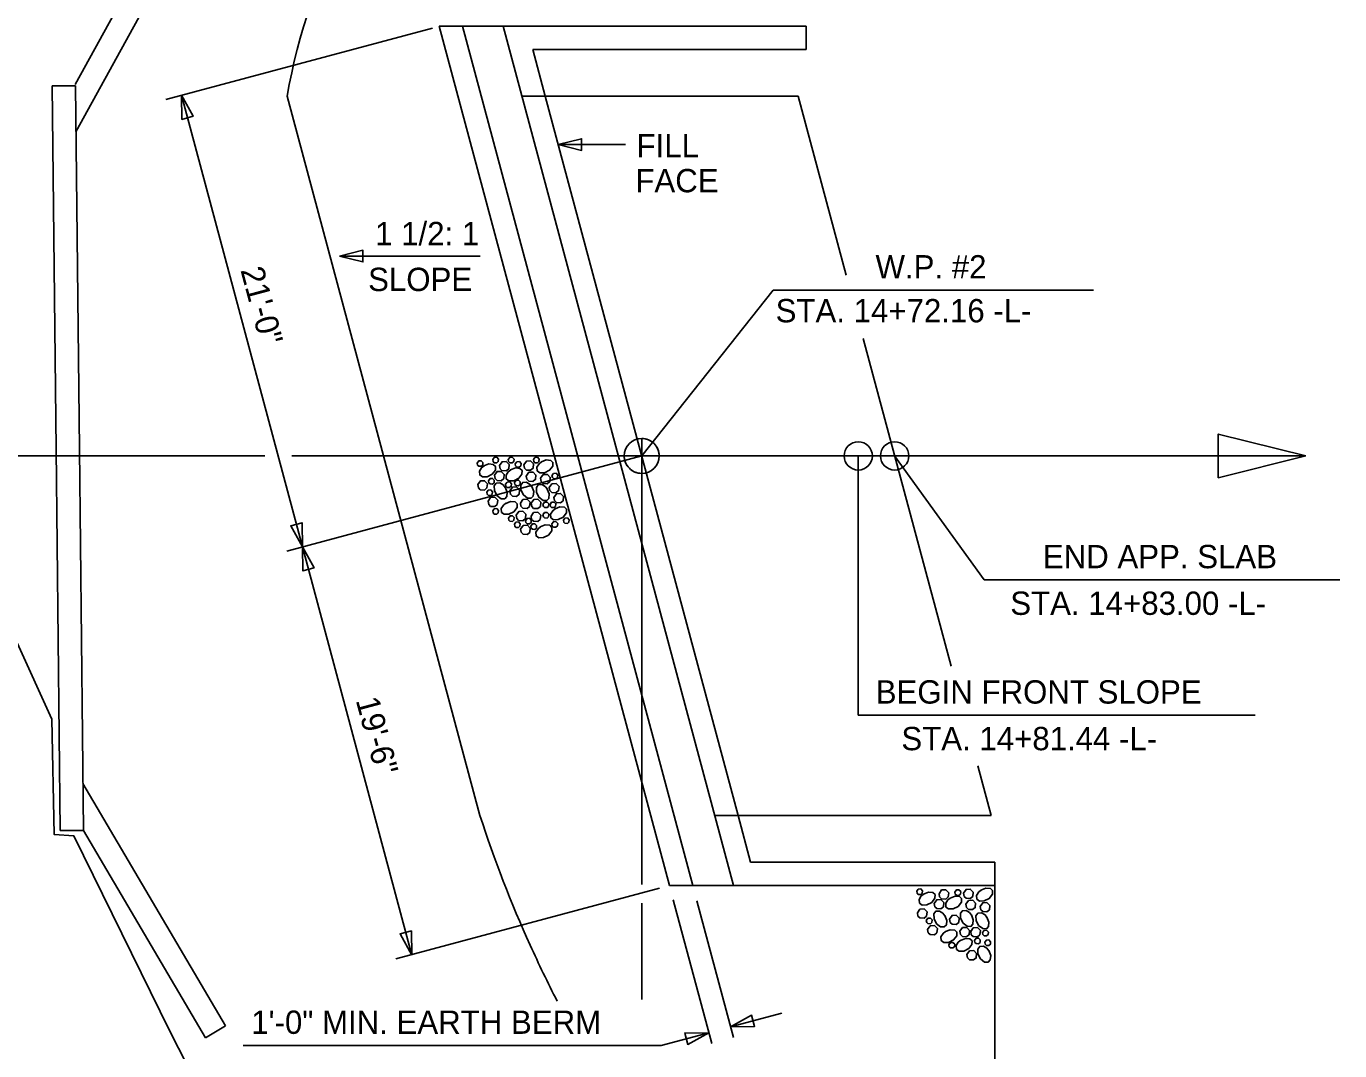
# Model space of a CAD drawing. Extents: x -20 to 509, y -659 to 21.
# Drawn here: x 139.4 to 195.7, y -130 to -86.1 of the extents above; entities that cross this region are included whole.
import ezdxf

# ---------------------------------------------------------------- set-up
doc = ezdxf.new("R2010")
doc.units = 0
for name, color, linetype in [('Arrowhead Terminators CELL', 7, 'Continuous'), ('Auto Dimensioning', 7, 'Continuous'), ('Dimension Lines', 7, 'Continuous'), ('Exist Hydro Stream or Body of Water', 7, 'Continuous'), ('Exist Structure Major Bridge Seam', 7, 'Continuous'), ('Mis Object Lines', 7, 'Continuous'), ('Mis Object Lines Hidden', 7, 'Continuous'), ('Mis Work Point CELL', 7, 'Continuous'), ('Miscellaneous Lines CELL', 7, 'Continuous'), ('Prop Horizontal Alignment', 7, 'Continuous'), ('Sup Concrete Girder Lines', 7, 'Continuous'), ('Text', 7, 'Continuous'), ('User Information Notes', 7, 'Continuous')]:
    doc.layers.add(name, color=color, linetype=linetype)

msp = doc.modelspace()

# ---------------------------------------------------------------- linework, layer by layer
at = {"layer": 'Arrowhead Terminators CELL'}
for points in [[(146.012, -89.031), (146.029, -90.062), (146.512, -89.933)], [(146.012, -89.031), (146.029, -90.062), (146.512, -89.933)], [(162.164, -91.147), (163.164, -91.397), (163.164, -90.897)], [(152.793, -95.923), (153.793, -95.673), (153.793, -96.173)], [(194.198, -104.489), (190.448, -103.552), (190.448, -105.427)], [(151.198, -108.386), (151.18, -107.355), (150.697, -107.484)], [(151.198, -108.386), (151.215, -109.416), (151.698, -109.287)], [(155.886, -125.884), (155.869, -124.853), (155.386, -124.982)], [(169.548, -128.965), (170.578, -128.948), (170.449, -128.465)], [(168.615, -129.215), (167.584, -129.232), (167.713, -129.715)]]:
    msp.add_lwpolyline(points, close=True, dxfattribs=at)
at = {"layer": 'Auto Dimensioning'}
for p, q in [((165.739, -104.989), (165.739, -122.863)), ((165.739, -123.655), (165.739, -127.786))]:
    msp.add_line(p, q, dxfattribs=at)
at = {"layer": 'Dimension Lines'}
for p, q in [((145.337, -89.212), (156.767, -86.149)), ((146.012, -89.031), (151.198, -108.386)), ((162.164, -91.147), (165.043, -91.147)), ((158.815, -95.923), (152.793, -95.923)), ((165.739, -104.489), (171.37, -97.384)), ((171.37, -97.384), (185.103, -97.384)), ((150.523, -108.566), (165.739, -104.489)), ((175.019, -104.489), (175.019, -115.606)), ((176.579, -104.489), (180.423, -109.804)), ((151.198, -108.386), (155.886, -125.884)), ((180.423, -109.804), (195.655, -109.804)), ((175.019, -115.606), (192.032, -115.606)), ((155.207, -126.045), (166.496, -123.02)), ((167.089, -123.522), (168.737, -129.671)), ((168.1, -123.562), (169.67, -129.421)), ((169.548, -128.965), (171.751, -128.375)), ((166.567, -129.764), (168.615, -129.215)), ((148.652, -129.764), (166.567, -129.764))]:
    msp.add_line(p, q, dxfattribs=at)
for centre in [(175.019, -104.489), (176.579, -104.489)]:
    msp.add_circle(centre, 0.606, dxfattribs=at)
at = {"layer": 'Exist Hydro Stream or Body of Water'}
msp.add_lwpolyline([(152.818, -143.472), (145.52, -129.155), (141.407, -120.782), (140.558, -120.72), (140.462, -115.767), (134.29, -102.218)], dxfattribs=at)
at = {"layer": 'Exist Structure Major Bridge Seam'}
for p, q in [((141.463, -88.566), (147.188, -78.13)), ((141.492, -90.593), (148.065, -78.611)), ((140.471, -88.632), (141.471, -88.632)), ((141.791, -118.53), (147.902, -128.926)), ((140.819, -120.55), (141.819, -120.55)), ((141.819, -120.55), (147.04, -129.433)), ((147.04, -129.433), (147.902, -128.926))]:
    msp.add_line(p, q, dxfattribs=at)
for points in [[(140.471, -88.632), (140.641, -104.206), (140.819, -120.55)], [(141.471, -88.632), (141.641, -104.206), (141.819, -120.55)]]:
    msp.add_lwpolyline(points, dxfattribs=at)
at = {"layer": 'Mis Object Lines'}
for p, q in [((157.055, -86.072), (172.789, -86.072)), ((157.055, -86.072), (166.924, -122.906)), ((158.055, -86.072), (167.924, -122.906)), ((159.805, -86.072), (169.674, -122.906)), ((172.789, -87.072), (172.789, -86.072)), ((161.072, -87.072), (161.608, -89.072)), ((161.072, -87.072), (172.789, -87.072)), ((172.448, -89.072), (160.608, -89.072)), ((172.448, -89.072), (174.504, -96.746)), ((175.231, -99.459), (178.995, -113.506)), ((180.14, -117.78), (180.71, -119.906)), ((180.71, -119.906), (168.87, -119.906)), ((169.87, -119.906), (170.406, -121.906)), ((180.87, -121.906), (170.406, -121.906)), ((180.87, -122.906), (180.87, -121.906)), ((166.924, -122.906), (180.87, -122.906))]:
    msp.add_line(p, q, dxfattribs=at)
at = {"layer": 'Mis Object Lines Hidden'}
msp.add_line((161.608, -89.072), (169.87, -119.906), dxfattribs=at)
at = {"layer": 'Mis Work Point CELL'}
for p, q in [((165.739, -103.739), (165.739, -104.489)), ((164.989, -104.489), (165.739, -104.489)), ((165.739, -104.489), (165.739, -105.239)), ((165.739, -104.489), (166.489, -104.489)), ((166.489, -104.489), (166.489, -104.489)), ((165.739, -105.239), (165.739, -105.239))]:
    msp.add_line(p, q, dxfattribs=at)
msp.add_circle((165.739, -104.489), 0.75, dxfattribs=at)
for start, end in [(359.997, 89.9989), (180.0011, 270.003)]:
    msp.add_arc((165.739, -104.489), 0.75, start, end, dxfattribs=at)
at = {"layer": 'Miscellaneous Lines CELL'}
for points in [[(158.686, -104.797), (158.753, -104.701), (158.861, -104.695), (158.935, -104.772), (158.924, -104.881), (158.858, -104.936), (158.752, -104.928), (158.702, -104.88), (158.686, -104.797)], [(159.355, -104.65), (159.422, -104.555), (159.529, -104.548), (159.604, -104.626), (159.593, -104.734), (159.527, -104.789), (159.421, -104.782), (159.371, -104.733), (159.355, -104.65)], [(160.018, -104.65), (160.085, -104.555), (160.192, -104.548), (160.267, -104.626), (160.256, -104.734), (160.19, -104.789), (160.084, -104.782), (160.034, -104.733), (160.018, -104.65)], [(160.687, -104.875), (160.799, -104.715), (160.978, -104.705), (161.103, -104.834), (161.085, -105.015), (160.974, -105.107), (160.797, -105.094), (160.714, -105.013), (160.687, -104.875)], [(161.098, -104.65), (161.165, -104.555), (161.272, -104.548), (161.347, -104.626), (161.336, -104.734), (161.27, -104.789), (161.164, -104.782), (161.114, -104.733), (161.098, -104.65)], [(161.439, -104.747), (161.649, -104.664), (161.841, -104.681), (161.933, -104.768), (161.93, -104.924), (161.791, -105.102), (161.576, -105.209), (161.374, -105.213), (161.26, -105.132), (161.249, -104.971), (161.342, -104.826), (161.448, -104.742)], [(158.976, -104.92), (159.186, -104.836), (159.378, -104.853), (159.47, -104.94), (159.467, -105.096), (159.328, -105.274), (159.114, -105.381), (158.911, -105.385), (158.797, -105.304), (158.787, -105.143), (158.879, -104.999), (158.985, -104.914)], [(159.429, -105.321), (159.541, -105.161), (159.72, -105.151), (159.845, -105.28), (159.827, -105.461), (159.716, -105.553), (159.539, -105.54), (159.456, -105.459), (159.429, -105.321)], [(159.64, -104.899), (159.752, -104.74), (159.931, -104.729), (160.055, -104.858), (160.037, -105.039), (159.927, -105.131), (159.75, -105.118), (159.667, -105.038), (159.64, -104.899)], [(160.115, -105.089), (160.325, -105.006), (160.517, -105.023), (160.609, -105.11), (160.606, -105.266), (160.467, -105.443), (160.252, -105.551), (160.05, -105.554), (159.936, -105.473), (159.925, -105.312), (160.018, -105.168), (160.124, -105.084)], [(160.32, -104.834), (160.387, -104.738), (160.495, -104.732), (160.569, -104.809), (160.558, -104.918), (160.492, -104.973), (160.386, -104.965), (160.336, -104.917), (160.32, -104.834)], [(160.793, -105.352), (160.905, -105.193), (161.084, -105.182), (161.208, -105.311), (161.19, -105.492), (161.079, -105.584), (160.903, -105.571), (160.82, -105.491), (160.793, -105.352)], [(161.893, -105.333), (161.96, -105.237), (162.068, -105.231), (162.142, -105.308), (162.132, -105.417), (162.065, -105.472), (161.959, -105.464), (161.909, -105.416), (161.893, -105.333)], [(158.711, -105.721), (158.823, -105.561), (159.002, -105.551), (159.126, -105.68), (159.108, -105.861), (158.998, -105.953), (158.821, -105.94), (158.738, -105.859), (158.711, -105.721)], [(159.172, -105.556), (159.24, -105.461), (159.347, -105.455), (159.422, -105.532), (159.411, -105.64), (159.344, -105.695), (159.238, -105.688), (159.189, -105.639), (159.172, -105.556)], [(159.887, -105.833), (159.97, -106.043), (159.953, -106.235), (159.866, -106.327), (159.71, -106.324), (159.533, -106.185), (159.425, -105.97), (159.422, -105.768), (159.503, -105.654), (159.664, -105.644), (159.808, -105.736), (159.892, -105.842)], [(159.906, -105.706), (159.973, -105.611), (160.081, -105.605), (160.155, -105.682), (160.144, -105.79), (160.078, -105.846), (159.972, -105.838), (159.922, -105.79), (159.906, -105.706)], [(160.088, -105.992), (160.2, -105.832), (160.379, -105.822), (160.504, -105.951), (160.486, -106.132), (160.375, -106.224), (160.198, -106.211), (160.115, -106.13), (160.088, -105.992)], [(160.285, -105.631), (160.352, -105.535), (160.459, -105.529), (160.534, -105.606), (160.523, -105.715), (160.457, -105.77), (160.351, -105.762), (160.301, -105.714), (160.285, -105.631)], [(161.026, -105.806), (161.109, -106.016), (161.092, -106.208), (161.005, -106.3), (160.849, -106.297), (160.671, -106.158), (160.564, -105.943), (160.561, -105.741), (160.642, -105.627), (160.803, -105.616), (160.947, -105.709), (161.031, -105.815)], [(161.69, -105.908), (161.773, -106.117), (161.757, -106.31), (161.67, -106.401), (161.513, -106.399), (161.336, -106.26), (161.228, -106.045), (161.225, -105.843), (161.306, -105.729), (161.467, -105.718), (161.611, -105.81), (161.695, -105.916)], [(161.405, -105.45), (161.517, -105.29), (161.696, -105.28), (161.821, -105.409), (161.803, -105.59), (161.692, -105.682), (161.515, -105.669), (161.432, -105.588), (161.405, -105.45)], [(161.778, -105.839), (161.891, -105.68), (162.069, -105.669), (162.194, -105.798), (162.176, -105.979), (162.065, -106.071), (161.889, -106.058), (161.806, -105.978), (161.779, -105.839)], [(159.096, -106.047), (159.163, -105.952), (159.27, -105.945), (159.345, -106.023), (159.334, -106.131), (159.268, -106.186), (159.162, -106.179), (159.112, -106.13), (159.096, -106.047)], [(159.153, -106.432), (159.265, -106.273), (159.444, -106.263), (159.568, -106.392), (159.55, -106.572), (159.44, -106.664), (159.263, -106.652), (159.18, -106.571), (159.153, -106.432)], [(160.537, -106.511), (160.649, -106.352), (160.828, -106.342), (160.952, -106.471), (160.934, -106.651), (160.824, -106.743), (160.647, -106.731), (160.564, -106.65), (160.537, -106.511)], [(160.998, -106.518), (161.11, -106.359), (161.289, -106.349), (161.413, -106.478), (161.395, -106.658), (161.284, -106.75), (161.108, -106.737), (161.025, -106.657), (160.998, -106.518)], [(161.974, -106.269), (162.086, -106.109), (162.265, -106.099), (162.39, -106.228), (162.372, -106.409), (162.261, -106.501), (162.084, -106.488), (162.001, -106.407), (161.974, -106.269)], [(159.355, -106.849), (159.422, -106.753), (159.529, -106.747), (159.604, -106.825), (159.593, -106.933), (159.527, -106.988), (159.421, -106.981), (159.371, -106.932), (159.355, -106.849)], [(159.912, -106.526), (160.121, -106.443), (160.314, -106.46), (160.405, -106.547), (160.402, -106.703), (160.264, -106.88), (160.049, -106.988), (159.847, -106.991), (159.733, -106.91), (159.722, -106.749), (159.814, -106.605), (159.92, -106.521)], [(160.355, -107.034), (160.467, -106.875), (160.646, -106.864), (160.77, -106.993), (160.752, -107.174), (160.642, -107.266), (160.465, -107.253), (160.382, -107.172), (160.355, -107.034)], [(160.994, -107.074), (161.106, -106.914), (161.285, -106.904), (161.41, -107.033), (161.392, -107.214), (161.281, -107.306), (161.104, -107.293), (161.021, -107.212), (160.994, -107.074)], [(161.507, -106.567), (161.575, -106.472), (161.682, -106.466), (161.757, -106.543), (161.746, -106.651), (161.68, -106.707), (161.574, -106.699), (161.524, -106.651), (161.508, -106.567)], [(161.507, -107.014), (161.575, -106.918), (161.682, -106.912), (161.757, -106.99), (161.746, -107.098), (161.68, -107.153), (161.574, -107.145), (161.524, -107.097), (161.508, -107.014)], [(161.811, -106.567), (161.878, -106.472), (161.986, -106.466), (162.06, -106.543), (162.049, -106.651), (161.983, -106.707), (161.877, -106.699), (161.827, -106.651), (161.811, -106.567)], [(162.024, -106.759), (162.233, -106.676), (162.426, -106.692), (162.518, -106.779), (162.515, -106.936), (162.376, -107.113), (162.161, -107.22), (161.959, -107.224), (161.845, -107.143), (161.834, -106.982), (161.927, -106.838), (162.032, -106.753)], [(160.027, -107.161), (160.094, -107.065), (160.202, -107.059), (160.276, -107.136), (160.265, -107.245), (160.199, -107.3), (160.093, -107.292), (160.043, -107.244), (160.027, -107.161)], [(160.28, -107.42), (160.347, -107.325), (160.455, -107.319), (160.529, -107.396), (160.518, -107.504), (160.452, -107.559), (160.346, -107.552), (160.296, -107.503), (160.28, -107.42)], [(160.548, -107.627), (160.66, -107.467), (160.839, -107.457), (160.964, -107.586), (160.946, -107.767), (160.835, -107.859), (160.658, -107.846), (160.575, -107.765), (160.548, -107.627)], [(160.759, -107.267), (160.826, -107.171), (160.934, -107.165), (161.008, -107.243), (160.998, -107.351), (160.931, -107.406), (160.825, -107.399), (160.775, -107.35), (160.759, -107.267)], [(160.986, -107.5), (161.053, -107.405), (161.16, -107.398), (161.235, -107.476), (161.224, -107.584), (161.158, -107.639), (161.052, -107.632), (161.002, -107.583), (160.986, -107.5)], [(161.392, -107.532), (161.601, -107.448), (161.794, -107.465), (161.885, -107.552), (161.882, -107.708), (161.743, -107.886), (161.529, -107.993), (161.326, -107.997), (161.213, -107.916), (161.202, -107.755), (161.294, -107.611), (161.4, -107.526)], [(161.891, -107.407), (161.958, -107.311), (162.065, -107.305), (162.14, -107.383), (162.129, -107.491), (162.063, -107.546), (161.957, -107.538), (161.907, -107.49), (161.891, -107.407)], [(162.383, -107.247), (162.451, -107.151), (162.558, -107.145), (162.633, -107.223), (162.622, -107.331), (162.555, -107.386), (162.449, -107.379), (162.4, -107.33), (162.383, -107.247)], [(177.527, -123.153), (177.594, -123.057), (177.702, -123.051), (177.776, -123.128), (177.765, -123.237), (177.699, -123.292), (177.593, -123.284), (177.543, -123.236), (177.527, -123.153)], [(177.817, -123.275), (178.027, -123.192), (178.22, -123.209), (178.311, -123.296), (178.308, -123.452), (178.169, -123.63), (177.955, -123.737), (177.752, -123.741), (177.638, -123.66), (177.628, -123.499), (177.72, -123.354), (177.826, -123.27)], [(178.481, -123.255), (178.593, -123.096), (178.772, -123.085), (178.897, -123.214), (178.879, -123.395), (178.768, -123.487), (178.591, -123.474), (178.508, -123.394), (178.481, -123.255)], [(179.161, -123.19), (179.228, -123.094), (179.336, -123.088), (179.41, -123.165), (179.399, -123.274), (179.333, -123.329), (179.227, -123.321), (179.177, -123.273), (179.161, -123.19)], [(179.528, -123.231), (179.64, -123.071), (179.819, -123.061), (179.944, -123.19), (179.926, -123.371), (179.815, -123.463), (179.638, -123.45), (179.555, -123.369), (179.528, -123.231)], [(180.28, -123.103), (180.49, -123.02), (180.682, -123.037), (180.774, -123.124), (180.771, -123.28), (180.632, -123.458), (180.417, -123.565), (180.215, -123.569), (180.101, -123.488), (180.09, -123.327), (180.183, -123.182), (180.289, -123.098)], [(178.27, -123.677), (178.382, -123.517), (178.561, -123.507), (178.686, -123.636), (178.668, -123.817), (178.557, -123.909), (178.381, -123.896), (178.297, -123.815), (178.271, -123.677)], [(178.956, -123.445), (179.166, -123.362), (179.358, -123.378), (179.45, -123.465), (179.447, -123.622), (179.308, -123.799), (179.093, -123.907), (178.891, -123.91), (178.777, -123.829), (178.766, -123.668), (178.859, -123.524), (178.965, -123.44)], [(179.634, -123.708), (179.746, -123.549), (179.925, -123.538), (180.049, -123.667), (180.031, -123.848), (179.921, -123.94), (179.744, -123.927), (179.661, -123.847), (179.634, -123.708)], [(180.246, -123.806), (180.358, -123.646), (180.537, -123.636), (180.662, -123.765), (180.644, -123.946), (180.533, -124.038), (180.356, -124.025), (180.273, -123.944), (180.246, -123.806)], [(177.552, -124.077), (177.664, -123.917), (177.843, -123.907), (177.967, -124.036), (177.949, -124.217), (177.839, -124.309), (177.662, -124.296), (177.579, -124.215), (177.552, -124.077)], [(177.937, -124.403), (178.004, -124.308), (178.111, -124.301), (178.186, -124.379), (178.175, -124.487), (178.109, -124.542), (178.003, -124.535), (177.953, -124.486), (177.937, -124.403)], [(178.728, -124.189), (178.811, -124.399), (178.795, -124.591), (178.708, -124.683), (178.551, -124.68), (178.374, -124.541), (178.266, -124.326), (178.263, -124.124), (178.344, -124.01), (178.505, -123.999), (178.649, -124.092), (178.733, -124.198)], [(178.929, -124.348), (179.041, -124.188), (179.22, -124.178), (179.345, -124.307), (179.327, -124.488), (179.216, -124.58), (179.04, -124.567), (178.956, -124.486), (178.929, -124.348)], [(179.867, -124.162), (179.95, -124.372), (179.933, -124.564), (179.846, -124.656), (179.69, -124.653), (179.513, -124.514), (179.405, -124.299), (179.402, -124.097), (179.483, -123.983), (179.644, -123.972), (179.788, -124.065), (179.872, -124.171)], [(180.531, -124.264), (180.614, -124.473), (180.598, -124.666), (180.511, -124.757), (180.354, -124.754), (180.177, -124.616), (180.07, -124.401), (180.066, -124.199), (180.147, -124.085), (180.308, -124.074), (180.452, -124.166), (180.537, -124.272)], [(177.994, -124.788), (178.106, -124.629), (178.285, -124.619), (178.409, -124.748), (178.391, -124.928), (178.281, -125.02), (178.104, -125.007), (178.021, -124.927), (177.994, -124.788)], [(178.753, -124.882), (178.962, -124.799), (179.155, -124.815), (179.246, -124.902), (179.244, -125.059), (179.105, -125.236), (178.89, -125.344), (178.688, -125.347), (178.574, -125.266), (178.563, -125.105), (178.655, -124.961), (178.761, -124.877)], [(179.378, -124.867), (179.49, -124.708), (179.669, -124.698), (179.793, -124.827), (179.775, -125.007), (179.665, -125.099), (179.488, -125.086), (179.405, -125.006), (179.378, -124.867)], [(179.839, -124.874), (179.951, -124.715), (180.13, -124.704), (180.254, -124.833), (180.236, -125.014), (180.126, -125.106), (179.949, -125.093), (179.866, -125.013), (179.839, -124.874)], [(180.349, -124.923), (180.416, -124.828), (180.523, -124.822), (180.598, -124.899), (180.587, -125.007), (180.521, -125.063), (180.415, -125.055), (180.365, -125.006), (180.349, -124.923)], [(178.904, -125.444), (178.971, -125.348), (179.078, -125.342), (179.153, -125.419), (179.142, -125.528), (179.076, -125.583), (178.97, -125.575), (178.92, -125.527), (178.904, -125.444)], [(179.403, -125.256), (179.613, -125.173), (179.805, -125.19), (179.897, -125.277), (179.894, -125.433), (179.755, -125.611), (179.54, -125.718), (179.338, -125.722), (179.224, -125.641), (179.213, -125.48), (179.306, -125.335), (179.412, -125.251)], [(180.002, -125.26), (180.069, -125.164), (180.176, -125.158), (180.251, -125.235), (180.24, -125.344), (180.174, -125.399), (180.068, -125.391), (180.018, -125.343), (180.002, -125.26)], [(180.612, -125.694), (180.696, -125.904), (180.679, -126.096), (180.592, -126.188), (180.436, -126.185), (180.258, -126.046), (180.151, -125.831), (180.147, -125.629), (180.228, -125.515), (180.389, -125.504), (180.533, -125.597), (180.618, -125.702)], [(180.443, -125.338), (180.51, -125.243), (180.618, -125.237), (180.692, -125.314), (180.682, -125.422), (180.615, -125.478), (180.509, -125.47), (180.459, -125.422), (180.443, -125.338)], [(179.678, -125.865), (179.79, -125.705), (179.969, -125.695), (180.093, -125.824), (180.075, -126.005), (179.964, -126.097), (179.788, -126.084), (179.705, -126.003), (179.678, -125.865)]]:
    msp.add_lwpolyline(points, dxfattribs=at)
at = {"layer": 'Prop Horizontal Alignment'}
for p, q in [((89.68, -104.489), (149.591, -104.489)), ((150.748, -104.489), (194.198, -104.489))]:
    msp.add_line(p, q, dxfattribs=at)
at = {"layer": 'Sup Concrete Girder Lines'}
for p, q in [((150.544, -89.072), (158.806, -119.906)), ((169.87, -122.906), (180.87, -122.906)), ((180.87, -122.906), (180.87, -148.463))]:
    msp.add_line(p, q, dxfattribs=at)
for centre, radius, start, end in [((172.847, -92.8), 22.612, 90.1461, 170.5127), ((209.68, -103.401), 53.484, 197.9743, 204.3637), ((209.68, -103.401), 53.484, 204.3637, 207.2118)]:
    msp.add_arc(centre, radius, start, end, dxfattribs=at)
at = {"layer": 'User Information Notes'}
msp.add_line((165.739, -104.489), (165.739, -104.489), dxfattribs=at)
msp.add_line((165.739, -104.489), (165.739, -104.489), dxfattribs=at)

# ---------------------------------------------------------------- texts
at = {"layer": 'Dimension Lines'}
for s, p in [('FILL', (165.518, -91.689)), ('FACE', (165.467, -93.189))]:
    msp.add_text(s, height=1, dxfattribs=at).set_placement(p)
for s, p in [('21\'-0"', (148.536, -96.522)), ('19\'-6"', (153.477, -114.959))]:
    msp.add_text(s, height=1, rotation=285, dxfattribs=at).set_placement(p)
at = {"layer": 'Text'}
for s, p in [('1 1/2: 1', (154.314, -95.458)), ('W.P. #2', (175.76, -96.884)), ('SLOPE', (154.013, -97.423)), ('STA. 14+72.16 -L-', (171.479, -98.764)), ('END APP. SLAB', (182.934, -109.304)), ('STA. 14+83.00 -L-', (181.536, -111.304)), ('BEGIN FRONT SLOPE', (175.768, -115.106)), ('STA. 14+81.44 -L-', (176.868, -117.106)), ('1\'-0" MIN. EARTH BERM', (149.004, -129.264))]:
    msp.add_text(s, height=1, dxfattribs=at).set_placement(p)

doc.saveas('drawing.dxf')
